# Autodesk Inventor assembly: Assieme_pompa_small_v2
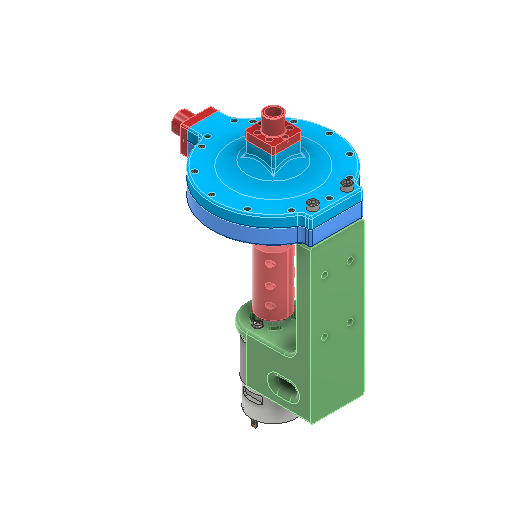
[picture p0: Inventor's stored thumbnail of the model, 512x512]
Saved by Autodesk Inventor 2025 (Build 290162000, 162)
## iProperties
Created: 2025-04
Part Number: Assieme_pompa_small_v2
Document SubType Name: Assembly
Designer: R5800u
Author: R5800u
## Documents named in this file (24)
- C:\Users\R5800u\Desktop\pompa centrifuga_small2\Assieme_pompa_small_v2.iam
- C:\Users\R5800u\Desktop\pompa centrifuga_small2\pompa centrifuga.ipt
- C:\Users\R5800u\Desktop\pompa centrifuga_small2\albero_12mm.ipt
- C:\Users\R5800u\Desktop\pompa centrifuga_small2\supporto_albero.ipt
- C:\Users\R5800u\Documents\Inventor\Content Center Files\R2025\it-IT\BS 290 SKF(30)\BS 290 SKF - SKF 625.ipt
- C:\Users\R5800u\Desktop\pompa centrifuga_small2\cassa_bassa.ipt
- C:\Users\R5800u\Desktop\pompa centrifuga_small2\cassa_alta.ipt
- C:\Users\R5800u\Documents\Inventor\Content Center Files\R2025\it-IT\AS 1420\AS 1420 - 1973 - M3 x 20.ipt
- C:\Users\R5800u\Documents\Inventor\Content Center Files\R2025\it-IT\AS 1112 (2)\AS 1112 - M3  Tipo 5.ipt
- C:\Users\R5800u\Desktop\pompa centrifuga_small2\out.ipt
- C:\Users\R5800u\Desktop\pompa centrifuga_small2\in.ipt
- C:\Users\R5800u\Documents\Inventor\Content Center Files\R2025\it-IT\AS 1420\AS 1420 - 1973 - M3 x 10.ipt
- C:\Users\R5800u\Desktop\pompa centrifuga_small2\autof - M3 x 8.ipt
- C:\Users\R5800u\Desktop\pompa centrifuga_small2\anello_5mm.ipt
- C:\Users\R5800u\Desktop\pompa centrifuga_small2\connettore_rigido.ipt
- C:\Users\R5800u\Desktop\pompa centrifuga_small2\rondella_5mm.ipt
- C:\Users\R5800u\Documents\Inventor\Content Center Files\R2025\it-IT\AS 1421(2)\AS 1421 - M3 x 4 Punta a coppa.ipt
- C:\Users\R5800u\Desktop\pompa centrifuga_small2\tappo_connettore_8mm.ipt
- C:\Users\R5800u\Desktop\pompa centrifuga_small2\775.ipt
- C:\Users\R5800u\Desktop\pompa centrifuga_small2\giunto01.ipt
- C:\Users\R5800u\Documents\Inventor\Content Center Files\R2025\it-IT\AS 1112 (2)\AS 1112 - M5  Tipo 5.ipt
- C:\Users\R5800u\Desktop\pompa centrifuga_small2\sostegno_775_02.ipt
- C:\Users\R5800u\Documents\Inventor\Content Center Files\R2025\it-IT\AS 1427(05)\AS 1427 - M4 x 6(5) II.ipt
- C:\Users\R5800u\Documents\Inventor\Content Center Files\R2025\it-IT\BS 4168(1)\BS 4168 - M5 x 30(1).ipt
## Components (46 placed, 23 different names)
1. pompa centrifuga:1 — Coincidente:18, Allineato:3, Coincidente:21
2. BS 290 SKF 625:2 — Rotazionale:4, Rotazionale:10
3. albero_12mm:1 — Coincidente:12, Allineato:3, Coincidente:21
4. supporto_albero:1 — Coincidente:12, Rotazionale:4, Rotazionale:5, Rotazionale:17, Rotazionale:18
5. cassa_bassa:1
6. cassa_alta:1
7. AS 1420 - Metrico M3 x 20:1
8. AS 1420 - Metrico M3 x 20:2
9. AS 1420 - Metrico M3 x 20:3
10. AS 1420 - Metrico M3 x 20:4
11. AS 1420 - Metrico M3 x 20:5
12. AS 1420 - Metrico M3 x 20:6
13. AS 1420 - Metrico M3 x 20:7
14. AS 1420 - Metrico M3 x 20:8
15. AS 1420 - Metrico M3 x 20:9
16. AS 1420 - Metrico M3 x 20:10
17. AS 1420 - Metrico M3 x 20:11
18. AS 1420 - Metrico M3 x 20:12
19. AS 1420 - Metrico M3 x 20:13
20. AS 1112 (2) - Metrico M3  Tipo 5:1 — Coincidente:17
21. out:1 — Coincidente:19, Coincidente:20, Rotazionale:14, Rigido:3
22. in:1 — Allineato:4, Rotazionale:7
23. AS 1112 (2) - Metrico M3  Tipo 5:2
24. AS 1112 (2) - Metrico M3  Tipo 5:3 — Rotazionale:5
25. AS 1420 - Metrico M3 x 10:1 — Rotazionale:6
26. autof - M3 x 8:1 — Rotazionale:7
27. rondella_5mm:1 — Rotazionale:10, Rotazionale:11, Rotazionale:19
28. connettore_rigido:1 — Rotazionale:11, Rigido:1, Rotazionale:12, Rigido:2
29. AS 1421 Punta a coppa - Metrico M3 x 4 Punta a coppa:2 — Rigido:1
30. tappo_connettore_8mm:2 — Rotazionale:12
31. AS 1421 Punta a coppa - Metrico M3 x 4 Punta a coppa:3 — Rigido:2
32. 775:1 — Angolo:3, Rotazionale:21, Rigido:4
33. autof - M3 x 8:2 — Rotazionale:14
34. BS 290 SKF 625:3 — Rotazionale:15, Rotazionale:16
35. anello_5mm:1 — Rotazionale:16
36. autof - M3 x 8:3 — Rigido:3
37. BS 290 SKF 625:4 — Rotazionale:18
38. rondella_5mm:2 — Rotazionale:19, Rotazionale:20
39. giunto01:1 — Rotazionale:20, Inserimento:15, Angolo:4
40. AS 1112 (2) - Metrico M5  Tipo 5:1 — Inserimento:15, Rigido:4
41. sostegno_775_02:1 — Rotazionale:21, Angolo:5, Rotazionale:26
42. BS 4168 : Parte 1 Vite con esagono incassato - Metrico M5 x 30:2
43. BS 4168 : Parte 1 Vite con esagono incassato - Metrico M5 x 30:1 — Rotazionale:25
44. AS 1427 H - Metrico M4 x 6:1
45. AS 1427 H - Metrico M4 x 6:2
46. AS 1112 (2) - Metrico M5  Tipo 5:2 — Rotazionale:26
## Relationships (33: RevoluteJoint 17, Mate 6, WeldJoint 4, Angle 3, Flush 2, Insert 1)
- Coincidente:12 [Mate]: albero_12mm:1 ↔ supporto_albero:1
- Rotazionale:4 [RevoluteJoint]: BS 290 SKF 625:2 ↔ supporto_albero:1
- Coincidente:17 [Mate]: AS 1112 (2) - Metrico M3  Tipo 5:1
- Coincidente:18 [Mate]: pompa centrifuga:1
- Coincidente:19 [Mate]: out:1
- Coincidente:20 [Mate]: out:1
- Allineato:3 [Flush]: pompa centrifuga:1 ↔ albero_12mm:1
- Allineato:4 [Flush]: in:1
- Rotazionale:5 [RevoluteJoint]: supporto_albero:1 ↔ AS 1112 (2) - Metrico M3  Tipo 5:3
- Rotazionale:6 [RevoluteJoint]: AS 1420 - Metrico M3 x 10:1
- Rotazionale:7 [RevoluteJoint]: in:1 ↔ autof - M3 x 8:1
- Rotazionale:10 [RevoluteJoint]: BS 290 SKF 625:2 ↔ rondella_5mm:1
- Rotazionale:11 [RevoluteJoint]: rondella_5mm:1 ↔ connettore_rigido:1
- Rigido:1 [WeldJoint]: connettore_rigido:1 ↔ AS 1421 Punta a coppa - Metrico M3 x 4 Punta a coppa:2
- Rotazionale:12 [RevoluteJoint]: connettore_rigido:1 ↔ tappo_connettore_8mm:2
- Rigido:2 [WeldJoint]: connettore_rigido:1 ↔ AS 1421 Punta a coppa - Metrico M3 x 4 Punta a coppa:3
- Angolo:3 [Angle]: 775:1
- Rotazionale:14 [RevoluteJoint]: out:1 ↔ autof - M3 x 8:2
- Rotazionale:15 [RevoluteJoint]: BS 290 SKF 625:3
- Rotazionale:16 [RevoluteJoint]: BS 290 SKF 625:3 ↔ anello_5mm:1
- Rotazionale:17 [RevoluteJoint]: supporto_albero:1
- Rigido:3 [WeldJoint]: out:1 ↔ autof - M3 x 8:3
- Rotazionale:18 [RevoluteJoint]: supporto_albero:1 ↔ BS 290 SKF 625:4
- Coincidente:21 [Mate]: pompa centrifuga:1 ↔ albero_12mm:1
- Rotazionale:19 [RevoluteJoint]: rondella_5mm:1 ↔ rondella_5mm:2
- Rotazionale:20 [RevoluteJoint]: rondella_5mm:2 ↔ giunto01:1
- Inserimento:15: giunto01:1 ↔ AS 1112 (2) - Metrico M5  Tipo 5:1
- Angolo:4 [Angle]: giunto01:1
- Rotazionale:21 [RevoluteJoint]: 775:1 ↔ sostegno_775_02:1
- Angolo:5 [Angle]: sostegno_775_02:1
- Rigido:4 [WeldJoint]: 775:1 ↔ AS 1112 (2) - Metrico M5  Tipo 5:1
- Rotazionale:25 [RevoluteJoint]: BS 4168 : Parte 1 Vite con esagono incassato - Metrico M5 x 30:1
- Rotazionale:26 [RevoluteJoint]: sostegno_775_02:1 ↔ AS 1112 (2) - Metrico M5  Tipo 5:2
